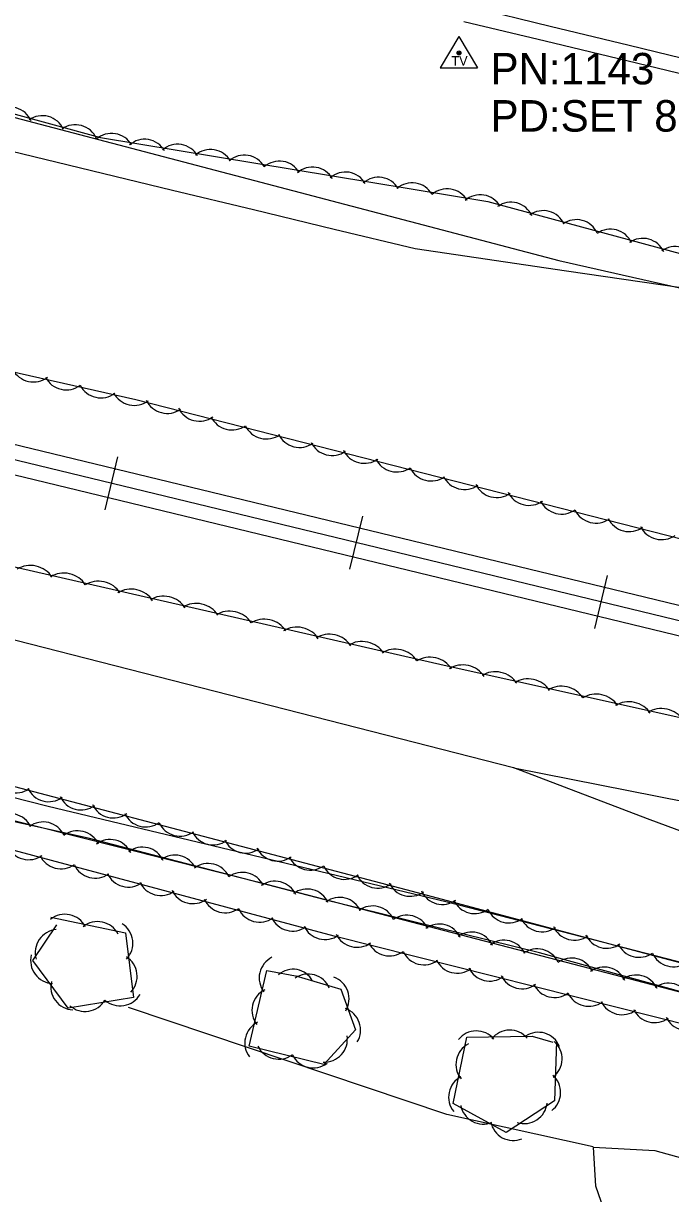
# Model space of a CAD drawing. Extents: x 1441650 to 1491889, y 345904 to 358319.
# Drawn here: x 1451579.7 to 1451682.5, y 352936.1 to 353122 of the extents above; entities that cross this region are included whole.
import ezdxf

# ---------------------------------------------------------------- set-up
doc = ezdxf.new("R2010")
doc.units = 0
for name, color, linetype in [('S_EDGE_PAVEMENT', 7, 'Continuous'), ('S_RAILROAD', 7, 'Continuous'), ('S_SECONDARY_CTL', 7, 'Continuous'), ('S_SECONDARY_CTL_ANNOT', 7, 'Continuous'), ('S_SHOULDER', 7, 'Continuous'), ('S_STREAM', 7, 'Continuous'), ('S_TREE', 7, 'Continuous')]:
    doc.layers.add(name, color=color, linetype=linetype)

msp = doc.modelspace()

# ---------------------------------------------------------------- linework, layer by layer
at = {"layer": 'S_EDGE_PAVEMENT'}
msp.add_lwpolyline([(1451650.85, 353124.64), (1451663.41, 353121.6), (1451675.96, 353118.56), (1451688.52, 353115.52), (1451701.07, 353112.49), (1451714.05, 353109.36), (1451727.03, 353106.24), (1451740.01, 353103.11), (1451752.99, 353099.99), (1451765.48, 353096.95), (1451777.98, 353093.92), (1451790.47, 353090.88)], dxfattribs=at)
at = {"layer": 'S_RAILROAD'}
for p, q in [((1451592.71, 353044.73), (1451594.75, 353053.16)), ((1451594.28, 353051.22), (1451594.25, 353051.12)), ((1451593.17, 353046.64), (1451593.18, 353046.68)), ((1451631.58, 353035.31), (1451633.63, 353043.74)), ((1451633.16, 353041.8), (1451633.13, 353041.7)), ((1451632.05, 353037.22), (1451632.05, 353037.26)), ((1451670.46, 353025.9), (1451672.5, 353034.33)), ((1451672.03, 353032.38), (1451672.01, 353032.28)), ((1451670.92, 353027.8), (1451670.93, 353027.84))]:
    msp.add_line(p, q, dxfattribs=at)
for points in [[(1452391.27, 352858.13), (1451315.37, 353118.79)], [(1452390.72, 352855.86), (1451314.82, 353116.52)], [(1452390.16, 352853.56), (1451314.26, 353114.21)], [(1451593.76, 353048.94), (1451593.73, 353048.95)], [(1451632.63, 353039.52), (1451632.6, 353039.53)], [(1451671.51, 353030.1), (1451671.48, 353030.11)]]:
    msp.add_lwpolyline(points, dxfattribs=at)
at = {"layer": 'S_SECONDARY_CTL'}
for p, q in [((1451648.91, 353119.95), (1451645.9, 353114.99)), ((1451648.91, 353119.95), (1451651.86, 353114.99)), ((1451645.9, 353114.99), (1451651.86, 353114.99))]:
    msp.add_line(p, q, dxfattribs=at)
for radius in [0.311, 0.183, 0.103]:
    msp.add_circle((1451648.91, 353117.34), radius, dxfattribs=at)
at = {"layer": 'S_SHOULDER'}
msp.add_lwpolyline([(1451649.7, 353122.35), (1451662.62, 353119.24), (1451675.54, 353116.13), (1451688.46, 353113.01), (1451701.38, 353109.9), (1451713.92, 353106.97), (1451726.46, 353104.03), (1451739, 353101.1), (1451751.54, 353098.17), (1451764.16, 353095.1), (1451776.78, 353092.03), (1451789.4, 353088.96)], dxfattribs=at)
at = {"layer": 'S_STREAM'}
for points in [[(1451383.13, 353155.3), (1451470.61, 353132.76), (1451570.07, 353109.24), (1451664.79, 353084.35), (1451749.91, 353065.07)], [(1451657.59, 353003.75), (1451515.17, 353040.18), (1451448.99, 353055.93)], [(1451790.54, 352936.77), (1451769.7, 352943.9), (1451742.69, 352952.54), (1451711.44, 352960.64), (1451661.72, 352974.37), (1451628.9, 352982.47), (1451590.03, 352992.6), (1451539.12, 353003.87), (1451494.17, 353015.26), (1451455.96, 353025.32), (1451404.93, 353038.26), (1451375.41, 353045.32)], [(1451396.96, 353043.5), (1451471.6, 353025.03), (1451506.9, 353018.33), (1451519.44, 353015.31), (1451538.04, 353009.28), (1451583.65, 352997.65), (1451616.17, 352989.86), (1451647.01, 352982.45), (1451713.3, 352965.34), (1451746.67, 352957.92), (1451755.06, 352957.9), (1451755.72, 352960.8), (1451752.66, 352964.42), (1451720.38, 352980.24), (1451678.85, 352995.65), (1451657.62, 353003.74), (1451716.81, 352992.06), (1451761.2, 352984.03), (1451829.92, 352966.49)], [(1451670.2, 352943.53), (1451647, 352948.68), (1451596.43, 352965.65)], [(1451686.05, 352899.89), (1451674.53, 352926.16), (1451670.65, 352937.26), (1451670.26, 352943.5), (1451680.01, 352942.94), (1451726.07, 352930.19), (1451766, 352921.18), (1451782.23, 352912.38), (1451801.16, 352907.65)]]:
    msp.add_lwpolyline(points, dxfattribs=at)
at = {"layer": 'S_TREE'}
for points in [[(1451355.34, 353161.79), (1451437.85, 353142.96), (1451514.28, 353125.15), (1451592, 353103.91), (1451653.51, 353093.73), (1451729.43, 353073.18), (1451756.76, 353072.92), (1451807.16, 353058.25)], [(1451487.74, 353123.46), (1451500.59, 353120.36), (1451513.45, 353117.26), (1451526.3, 353114.16), (1451539.15, 353111.06), (1451552, 353107.96), (1451564.85, 353104.86), (1451577.7, 353101.76), (1451590.55, 353098.66), (1451603.4, 353095.56), (1451616.25, 353092.46), (1451629.1, 353089.36), (1451641.95, 353086.26), (1451665.98, 353082.74), (1451690, 353079.23), (1451714.03, 353075.71), (1451738.05, 353072.2), (1451740.44, 353054.71), (1451742.83, 353037.22)], [(1451487.74, 353123.46), (1451500.59, 353120.36), (1451513.45, 353117.26), (1451526.3, 353114.16), (1451539.15, 353111.06), (1451552, 353107.96), (1451564.85, 353104.86), (1451577.7, 353101.76), (1451590.55, 353098.66), (1451603.4, 353095.56), (1451616.25, 353092.46), (1451629.1, 353089.36), (1451641.95, 353086.26), (1451665.98, 353082.74), (1451690, 353079.23), (1451714.03, 353075.71), (1451738.05, 353072.2), (1451740.44, 353054.71), (1451742.83, 353037.22)], [(1452399.14, 352860.23), (1452392.79, 352867.03), (1452382.12, 352869.59), (1452327.3, 352883.47), (1452173.6, 352920.35), (1452113.09, 352935.02), (1451909.03, 352985.34), (1451768.73, 353018.48), (1451597.59, 353062.21), (1451520.63, 353079.57), (1451497.6, 353087.01), (1451451.58, 353107.05), (1451431.16, 353111.57), (1451407.97, 353109.12), (1451350.29, 353121.94)], [(1451327.8, 353097.43), (1451402.02, 353075.91), (1451483.15, 353063.22), (1451576.93, 353036.02), (1451646.54, 353020.05), (1451689.99, 353010.43), (1451796.02, 352984.25), (1451899.97, 352960.18), (1451949.9, 352948.34), (1452006.53, 352935.3), (1452073.14, 352918.73), (1452124.03, 352905.6), (1452167.72, 352893.63), (1452197.97, 352887.99), (1452238.01, 352878.56), (1452281.14, 352868.99), (1452322.62, 352858.1), (1452348, 352852.48), (1452371.02, 352846.3), (1452385.26, 352842.85), (1452392.41, 352843.39), (1452396.82, 352844.8), (1452398.6, 352846.57)], [(1451805.02, 352950.99), (1451762.83, 352955.93), (1451724.36, 352962.04), (1451640.54, 352984.37), (1451553.19, 353007.33), (1451413.75, 353041.69), (1451358.67, 353056.02), (1451302.51, 353070.69)], [(1451797.66, 352930.1), (1451735.74, 352948.75), (1451686.19, 352962.59), (1451629.07, 352976.98), (1451546.77, 352999.02), (1451506.2, 353008), (1451404.42, 353032.97), (1451405.49, 353036.33), (1451432.43, 353030.37), (1451508.75, 353012.42), (1451559.49, 353000.11), (1451616.93, 352985.63), (1451676.07, 352970.2), (1451740.6, 352953.27), (1451780.24, 352943.4), (1451805.43, 352935.24)], [(1451584.11, 352980.01), (1451595.96, 352977.53), (1451597.22, 352967.25), (1451586.86, 352965.55), (1451581.21, 352973.12), (1451585.07, 352978.82)], [(1451622.98, 352970.68), (1451630.16, 352968.59), (1451632.45, 352962.11), (1451627.43, 352956.6), (1451615.61, 352959.52), (1451618.4, 352971.55), (1451623.52, 352970.59)], [(1451664.38, 352960.24), (1451664.1, 352950.83), (1451656.39, 352945.81), (1451647.96, 352950.41), (1451650.18, 352960.95), (1451660.54, 352961.12), (1451663.79, 352960.14)]]:
    msp.add_lwpolyline(points, dxfattribs=at)
for centre, major_axis, ratio, start_param, end_param in [((1451577.63, 353105.09), (-3.25, 1.66), 0.997346, 4.031241, 5.804441), ((1451582.75, 353103.73), (-3.25, 1.66), 0.997346, 4.031241, 5.804441), ((1451588, 353102.29), (-3.25, 1.66), 0.997346, 4.031241, 5.804441), ((1451593.75, 353100.93), (-3.42, 1.24), 0.997384, 4.010293, 5.783494), ((1451599, 353099.99), (-3.42, 1.24), 0.997384, 4.010293, 5.783494), ((1451604.23, 353099.2), (-3.42, 1.24), 0.997384, 4.010293, 5.783494), ((1451609.46, 353098.37), (-3.42, 1.24), 0.997384, 4.010293, 5.783494), ((1451614.83, 353097.48), (-3.42, 1.24), 0.997384, 4.010293, 5.783494), ((1451620.4, 353096.52), (-3.42, 1.24), 0.997384, 4.010293, 5.783494), ((1451625.65, 353095.58), (-3.42, 1.24), 0.997384, 4.010293, 5.783494), ((1451630.87, 353094.79), (-3.42, 1.24), 0.997384, 4.010293, 5.783494), ((1451636.11, 353093.96), (-3.42, 1.24), 0.997384, 4.010293, 5.783494), ((1451641.47, 353093.07), (-3.42, 1.24), 0.997384, 4.010293, 5.783494), ((1451647.04, 353092.11), (-3.42, 1.24), 0.997384, 4.010293, 5.783494), ((1451652.29, 353091.17), (-3.42, 1.24), 0.997384, 4.010293, 5.783494), ((1451657.16, 353090), (-3.49, 1.03), 0.997455, 3.848257, 5.621458), ((1451662.28, 353088.65), (-3.49, 1.03), 0.997455, 3.848257, 5.621458), ((1451667.54, 353087.22), (-3.49, 1.03), 0.997455, 3.848257, 5.621458), ((1451672.98, 353085.71), (-3.49, 1.03), 0.997455, 3.848257, 5.621458), ((1451678.11, 353084.25), (-3.49, 1.03), 0.997455, 3.848257, 5.621458), ((1451683.23, 353082.94), (-3.49, 1.03), 0.997455, 3.848257, 5.621458), ((1451581.32, 353068.61), (3.58, -0.7), 0.973751, 3.795531, 5.568732), ((1451586.51, 353067.36), (3.58, -0.7), 0.973751, 3.795531, 5.568732), ((1451592.01, 353066.09), (3.58, -0.7), 0.973751, 3.795531, 5.568732), ((1451597.32, 353064.89), (3.58, -0.7), 0.973751, 3.795531, 5.568732), ((1451602.53, 353063.62), (3.51, -0.98), 0.973746, 3.847136, 5.620337), ((1451607.67, 353062.38), (3.51, -0.98), 0.973746, 3.847136, 5.620337), ((1451612.82, 353060.99), (3.51, -0.98), 0.973746, 3.847136, 5.620337), ((1451618.28, 353059.56), (3.51, -0.98), 0.973746, 3.847136, 5.620337), ((1451623.55, 353058.21), (3.51, -0.98), 0.973746, 3.847136, 5.620337), ((1451628.7, 353056.93), (3.51, -0.98), 0.973746, 3.847136, 5.620337), ((1451633.84, 353055.69), (3.51, -0.98), 0.973746, 3.847136, 5.620337), ((1451638.99, 353054.31), (3.51, -0.98), 0.973746, 3.847136, 5.620337), ((1451644.45, 353052.88), (3.51, -0.98), 0.973746, 3.847136, 5.620337), ((1451649.72, 353051.53), (3.51, -0.98), 0.973746, 3.847136, 5.620337), ((1451654.87, 353050.25), (3.51, -0.98), 0.973746, 3.847136, 5.620337), ((1451660, 353049.01), (3.51, -0.98), 0.973746, 3.847136, 5.620337), ((1451665.16, 353047.62), (3.51, -0.98), 0.973746, 3.847136, 5.620337), ((1451670.62, 353046.19), (3.51, -0.98), 0.973746, 3.847136, 5.620337), ((1451675.89, 353044.84), (3.51, -0.98), 0.973746, 3.847136, 5.620337), ((1451681.04, 353043.56), (3.51, -0.98), 0.973746, 3.847136, 5.620337), ((1451581.07, 353032.77), (-3.55, 0.81), 0.854368, 3.825789, 5.598989), ((1451586.37, 353031.55), (-3.55, 0.81), 0.854368, 3.825789, 5.598989), ((1451591.87, 353030.26), (-3.55, 0.81), 0.854368, 3.825789, 5.598989), ((1451597.06, 353029.01), (-3.55, 0.81), 0.854368, 3.825789, 5.598989), ((1451602.22, 353027.89), (-3.55, 0.81), 0.854368, 3.825789, 5.598989), ((1451607.4, 353026.73), (-3.55, 0.81), 0.854368, 3.825789, 5.598989), ((1451612.7, 353025.51), (-3.55, 0.81), 0.854368, 3.825789, 5.598989), ((1451618.2, 353024.22), (-3.55, 0.81), 0.854368, 3.825789, 5.598989), ((1451623.38, 353022.97), (-3.55, 0.81), 0.854368, 3.825789, 5.598989), ((1451628.54, 353021.84), (-3.55, 0.81), 0.854368, 3.825789, 5.598989), ((1451633.72, 353020.69), (-3.55, 0.81), 0.854368, 3.825789, 5.598989), ((1451639.02, 353019.47), (-3.55, 0.81), 0.854368, 3.825789, 5.598989), ((1451644.52, 353018.18), (-3.55, 0.81), 0.854368, 3.825789, 5.598989), ((1451649.73, 353016.95), (-3.56, 0.79), 0.854394, 3.825789, 5.598989), ((1451654.9, 353015.87), (-3.56, 0.79), 0.854394, 3.825789, 5.598989), ((1451660.09, 353014.75), (-3.56, 0.79), 0.854394, 3.825789, 5.598989), ((1451665.4, 353013.57), (-3.56, 0.79), 0.854394, 3.825789, 5.598989), ((1451670.91, 353012.32), (-3.56, 0.79), 0.854394, 3.825789, 5.598989), ((1451676.1, 353011.11), (-3.56, 0.79), 0.854394, 3.825789, 5.598989), ((1451681.27, 353010.03), (-3.56, 0.79), 0.854394, 3.825789, 5.598989), ((1451578.49, 353003.39), (3.64, 0), 0.999871, 3.568311, 5.341512), ((1451583.75, 353002.01), (3.64, 0), 0.999871, 3.568311, 5.341512), ((1451588.89, 353000.69), (3.64, 0), 0.999871, 3.568311, 5.341512), ((1451594.02, 352999.42), (3.64, 0), 0.999871, 3.568311, 5.341512), ((1451577.6, 352992.84), (-3.45, 1.18), 0.998639, 3.909985, 5.683185), ((1451599.16, 352998), (3.64, 0), 0.999871, 3.568311, 5.341512), ((1451582.88, 352991.51), (-3.45, 1.18), 0.998639, 3.909985, 5.683185), ((1451588.34, 352990.1), (-3.45, 1.18), 0.998639, 3.909985, 5.683185), ((1451604.61, 352996.53), (3.64, 0), 0.999871, 3.568311, 5.341512), ((1451593.5, 352988.72), (-3.45, 1.18), 0.998639, 3.909985, 5.683185), ((1451609.88, 352995.14), (3.64, 0), 0.999871, 3.568311, 5.341512), ((1451615.02, 352993.83), (3.64, 0), 0.999871, 3.568311, 5.341512), ((1451580.57, 352992.79), (3.46, -1.15), 0.99864, 3.886085, 5.659286), ((1451598.64, 352987.5), (-3.45, 1.18), 0.998639, 3.909985, 5.683185), ((1451603.79, 352986.24), (-3.45, 1.18), 0.998639, 3.909985, 5.683185), ((1451620.14, 352992.56), (3.64, 0), 0.999871, 3.568311, 5.341512), ((1451585.7, 352991.34), (3.46, -1.15), 0.99864, 3.886085, 5.659286), ((1451591.15, 352989.85), (3.46, -1.15), 0.99864, 3.886085, 5.659286), ((1451609.07, 352984.91), (-3.45, 1.18), 0.998639, 3.909985, 5.683185), ((1451625.28, 352991.13), (3.64, 0), 0.999871, 3.568311, 5.341512), ((1451630.74, 352989.67), (3.64, 0), 0.999871, 3.568311, 5.341512), ((1451596.4, 352988.44), (3.46, -1.15), 0.99864, 3.886085, 5.659286), ((1451614.53, 352983.5), (-3.45, 1.18), 0.998639, 3.909985, 5.683185), ((1451636, 352988.28), (3.64, 0), 0.999871, 3.568311, 5.341512), ((1451601.54, 352987.1), (3.46, -1.15), 0.99864, 3.886085, 5.659286), ((1451619.66, 352982.1), (-3.53, 0.92), 0.998646, 3.825789, 5.598989), ((1451624.79, 352980.84), (-3.53, 0.92), 0.998646, 3.825789, 5.598989), ((1451641.14, 352986.97), (3.64, 0), 0.999871, 3.568311, 5.341512), ((1451606.66, 352985.81), (3.46, -1.15), 0.99864, 3.886085, 5.659286), ((1451611.79, 352984.36), (3.46, -1.15), 0.99864, 3.886085, 5.659286), ((1451629.93, 352979.53), (-3.53, 0.92), 0.998646, 3.825789, 5.598989), ((1451646.27, 352985.68), (3.52, -0.94), 0.999879, 3.825789, 5.598989), ((1451651.41, 352984.23), (3.52, -0.94), 0.999879, 3.825789, 5.598989), ((1451617.24, 352982.86), (3.46, -1.15), 0.99864, 3.886085, 5.659286), ((1451635.19, 352978.16), (-3.53, 0.92), 0.998646, 3.825789, 5.598989), ((1451656.85, 352982.75), (3.52, -0.94), 0.999879, 3.825789, 5.598989), ((1451586.33, 352976.83), (-3.57, 0.75), 0.99994, 3.825789, 5.598989), ((1451591.53, 352975.67), (-3.57, 0.75), 0.99994, 3.825789, 5.598989), ((1451593.48, 352975.89), (-3.42, 1.25), 0.999938, 2.727919, 4.50112), ((1451622.49, 352981.45), (3.46, -1.15), 0.99864, 3.886085, 5.659286), ((1451640.65, 352976.7), (-3.53, 0.92), 0.998646, 3.825789, 5.598989), ((1451645.79, 352975.28), (-3.53, 0.92), 0.998646, 3.825789, 5.598989), ((1451662.11, 352981.34), (3.52, -0.94), 0.999879, 3.825789, 5.598989), ((1451585.26, 352974.41), (-0.7, -3.58), 0.999996, 3.422624, 5.195824), ((1451627.63, 352980.11), (3.46, -1.15), 0.99864, 3.886085, 5.659286), ((1451632.72, 352978.87), (3.48, -1.07), 0.998645, 3.87718, 5.650381), ((1451650.92, 352974.02), (-3.53, 0.92), 0.998646, 3.825789, 5.598989), ((1451667.24, 352980.01), (3.52, -0.94), 0.999879, 3.825789, 5.598989), ((1451672.37, 352978.72), (3.52, -0.94), 0.999879, 3.825789, 5.598989), ((1451637.88, 352977.5), (3.48, -1.07), 0.998645, 3.87718, 5.650381), ((1451656.06, 352972.71), (-3.53, 0.92), 0.998646, 3.825789, 5.598989), ((1451661.33, 352971.34), (-3.53, 0.92), 0.998646, 3.825789, 5.598989), ((1451677.5, 352977.28), (3.52, -0.94), 0.999879, 3.825789, 5.598989), ((1451584.52, 352973.13), (2.18, -2.92), 0.999957, 3.825789, 5.598989), ((1451594.16, 352970.63), (-3.42, 1.25), 0.999938, 2.727919, 4.50112), ((1451620.82, 352970.38), (-3.12, -1.88), 0.999571, 4.627815, 6.401016), ((1451643.34, 352976.09), (3.48, -1.07), 0.998645, 3.87718, 5.650381), ((1451666.78, 352969.88), (-3.53, 0.92), 0.998646, 3.825789, 5.598989), ((1451682.95, 352975.79), (3.52, -0.94), 0.999879, 3.825789, 5.598989), ((1451622.55, 352968.1), (-0.34, -3.63), 0.968003, 2.167153, 3.940354), ((1451648.62, 352974.76), (3.48, -1.07), 0.998645, 3.87718, 5.650381), ((1451653.77, 352973.5), (3.48, -1.07), 0.998645, 3.87718, 5.650381), ((1451671.93, 352968.46), (-3.53, 0.92), 0.998646, 3.825789, 5.598989), ((1451587.74, 352968.94), (2.18, -2.92), 0.999957, 3.825789, 5.598989), ((1451624.95, 352967.34), (-3.5, 1.02), 0.999802, 3.825789, 5.598989), ((1451627.81, 352967.04), (-2.39, 2.75), 0.99998, 3.451562, 5.224762), ((1451658.91, 352972.28), (3.48, -1.07), 0.998645, 3.87718, 5.650381), ((1451677.05, 352967.2), (-3.52, 0.92), 0.998646, 3.825789, 5.598989), ((1451682.19, 352965.89), (-3.52, 0.92), 0.998646, 3.825789, 5.598989), ((1451595.1, 352969.57), (3.59, 0.59), 0.999953, 3.825789, 5.598989), ((1451619.66, 352965.21), (-3.12, -1.88), 0.999571, 4.627815, 6.401016), ((1451664.07, 352970.9), (3.48, -1.07), 0.998645, 3.87718, 5.650381), ((1451669.53, 352969.49), (3.48, -1.07), 0.998645, 3.87718, 5.650381), ((1451589.52, 352968.68), (3.59, 0.59), 0.999953, 3.825789, 5.598989), ((1451674.81, 352968.16), (3.48, -1.07), 0.998645, 3.87718, 5.650381), ((1451629.64, 352962.08), (-2.39, 2.75), 0.99998, 3.451562, 5.224762), ((1451679.96, 352966.9), (3.48, -1.07), 0.998645, 3.87718, 5.650381), ((1451685.1, 352965.68), (3.48, -1.07), 0.998645, 3.87718, 5.650381), ((1451618.53, 352960.05), (-3.12, -1.88), 0.999571, 4.627815, 6.401016), ((1451656.96, 352958.44), (0.11, -3.64), 0.996461, 2.240392, 4.013592), ((1451627.55, 352960.64), (2.45, 2.69), 0.999607, 3.825789, 5.598989), ((1451651.68, 352958.31), (0.11, -3.64), 0.996461, 2.240392, 4.013592), ((1451661.5, 352958.09), (-1.04, -3.49), 0.991375, 2.251018, 4.024218), ((1451661.64, 352957.5), (3.28, 1.59), 0.999989, 4.915081, 6.688282), ((1451620.28, 352961.11), (3.36, 1.42), 0.999664, 3.183424, 4.956624), ((1451652.07, 352956.64), (3.61, -0.48), 0.999504, 2.18029, 3.953491), ((1451625.76, 352959.72), (3.36, 1.42), 0.999664, 3.183424, 4.956624), ((1451650.9, 352951.44), (3.61, -0.48), 0.999504, 2.18029, 3.953491), ((1451661.41, 352952.17), (3.28, 1.59), 0.999989, 4.915081, 6.688282), ((1451652.76, 352950.79), (1.76, 3.19), 0.999997, 2.26183, 4.03503), ((1451659.28, 352950.87), (-0.39, 3.62), 0.999988, 2.724656, 4.497857), ((1451657.53, 352948.18), (1.76, 3.19), 0.999997, 2.26183, 4.03503)]:
    msp.add_ellipse(centre, major_axis=major_axis, ratio=ratio, start_param=start_param, end_param=end_param, dxfattribs=at)

# ---------------------------------------------------------------- texts
at = {"layer": 'S_SECONDARY_CTL'}
msp.add_text('TV', height=1.5, rotation=360, dxfattribs=at).set_placement((1451647.71, 353115.33))
at = {"layer": 'S_SECONDARY_CTL_ANNOT'}
for s, p in [('PN:1143', (1451653.91, 353112.34)), ('PD:SET 8" NAIL TRIG ELEV', (1451653.91, 353104.84))]:
    msp.add_text(s, height=5, dxfattribs=at).set_placement(p)

doc.saveas('drawing.dxf')
